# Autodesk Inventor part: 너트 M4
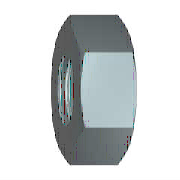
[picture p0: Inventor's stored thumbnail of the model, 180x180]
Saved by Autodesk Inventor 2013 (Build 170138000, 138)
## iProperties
Created: 2012-02
Part Number: 너트 M4
Material: 강철, 연강
Description: 6각 너트 및 6각 가는 너트 - 스타일 1
Document SubType Name: Modeling
Standard: KS B 1012
Designer: mduedu
Standards Organization: KS
Language: ko-KR
Size Designation: A M4
Categories: <MemberInstance><Categories><Category DisplayName="조임쇠" InternalName="e4da775c-781d-43d5-af7c-5136215cf5a6" Mnemonic="FSTN"><Category DisplayName="너트" InternalN
Density: 1 g/cm^3
IsCustomPart: 0
Author: mduedu
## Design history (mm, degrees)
sketch "스케치1"
  geometry: L1 (-4.041, 0)-(-2.021, 3.5); L2 (-2.021, 3.5)-(2.021, 3.5); L3 (2.021, 3.5)-(4.041, 0); L4 (4.041, 0)-(2.021, -3.5); L5 (2.021, -3.5)-(-2.021, -3.5); L6 (-2.021, -3.5)-(-4.041, 0); 2 further points
  constraints: 12 end point, 1 coincident, 1 horizontal, 11 other
  dimensions: "d0" = 8.0829 distance of L3.end L1.start (= 1.1547 x SW)
extrude "본체" new body sketch "스케치1" distance "d1" = 3.2 (= KOH); taper "d2" = 0 deg
sketch "스케치2"
  geometry: L1 (0, 2.021)-(0, 4.041) reference; L2 (0, 4.041)-(3.2, 4.041) reference; L3 (3.2, 2.021)-(3.2, 4.041) reference; L4 (-0.64, 0)-(3.84, 0) reference; L5 (0.313, 4.041)-(0, 3.5); L6 (2.887, 4.041)-(3.2, 3.5)
  constraints: 4 end point, 4 point on line
  dimensions: "d3" = 30 deg angle of L1 L5 (= ANG1); "d4" = 30 deg angle of L3 L6 (= ANG2); "d5" = 7 diameter of L5.end L4 (= SW0); "d6" = 7 diameter of L6.end L4 (= SW01)
revolve "모따기1" sketch "스케치2" stored, may be unused: angle "d7" = 90 deg
sketch "스케치3"
  geometry: A1 r 3.5 centre (0, 0) between (-1.75, -3.031) and (1.75, -3.031) reference; 1 further point
  constraints: 1 coincident
hole "스레드" sketch "스케치3" at (0, 0) diameter "d25" = 3.242; stored, may be unused: countersink angle "d29" = 82 deg, drill point angle "d31" = 118 deg; dims "d26" = 6, "d27" = 4, "d28" = 2, "d30" = 8
workaxis "Work Axis1"
workplane "Work Plane1"
body "Solid1"
chamfer "모따기2" distance "d8" = 0.37889 (= -0.5 x GD1 + 0.5 x NND); stored, may be unused: angle "d9" = 30 deg, second distance "d40" = 0.37889 (= -0.5 x GD1 + 0.5 x NND)
chamfer "모따기3" distance "d10" = 0.37889 (= -0.5 x GD1 + 0.5 x NND); stored, may be unused: angle "d11" = 30 deg, second distance "d41" = 0.37889 (= -0.5 x GD1 + 0.5 x NND)
other parameters: "ANG1" = 30 deg [user parameter; used in 1 equation term], "ANG2" = 30 deg [user parameter; used in 1 equation term], "NND" = 4 [user parameter; used in 4 equation terms], "KOH" = 3.2 [user parameter; used in 1 equation term], "SW" = 7 [user parameter; used in 4 equation terms], "SW0" = 7 (= SW) [user parameter; used in 1 equation term], "SW01" = 7 (= SW) [user parameter; used in 1 equation term], "GD1" = 3.24223 (computed from THREADDIA, PTC, TOA) [user parameter; used in 4 equation terms], "d13" = 0, "d14" = 0, "d39" = 0, "d42" = 0, "GUL" = 0.37889 (= 0.541266 x PTC) [user parameter], "TPU" = 14.28571 (computed from PTC) [user parameter], "THREADDIA" = 4 [user parameter; used in 1 equation term], "TOA" = 30 deg [user parameter; used in 1 equation term], "PTC" = 0.7 [user parameter; used in 4 equation terms], "E0" = 8.085 (= 1.155 x SW) [user parameter], "GAL" = 0.37889 (= 0.541266 x PTC) [user parameter]
